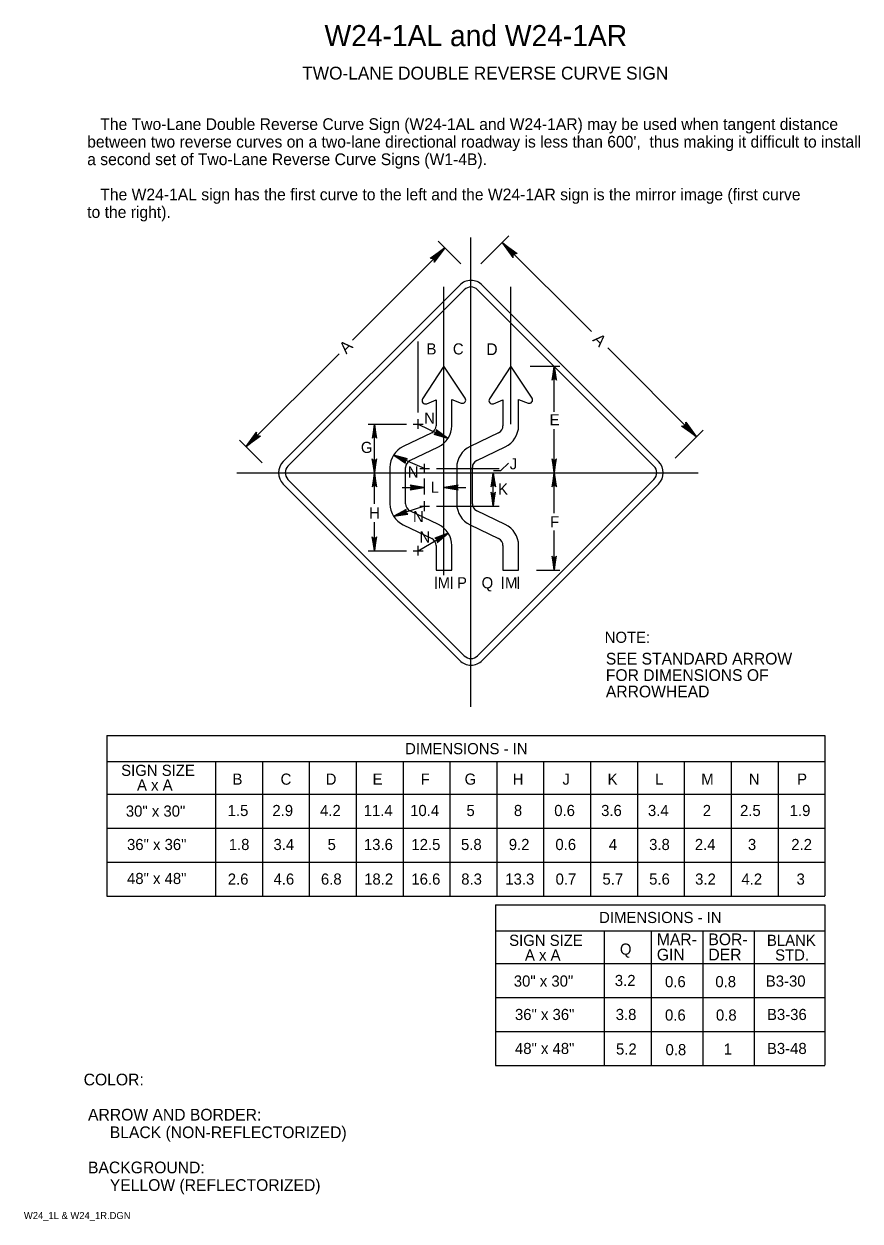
# Model space of a CAD drawing. Extents: x -0.124 to 0.191, y 0.004 to 0.276.
# Drawn here: x 0.0125 to 0.1908, y 0.0039 to 0.2592 of the extents above; entities that cross this region are included whole.
import ezdxf

# ---------------------------------------------------------------- set-up
doc = ezdxf.new("R2010")
doc.units = 0
for name, color, linetype in [('1', 7, 'Continuous'), ('2', 7, 'Continuous'), ('3', 7, 'Continuous')]:
    doc.layers.add(name, color=color, linetype=linetype)

# ---------------------------------------------------------------- blocks, each defined once
blk = doc.blocks.new('RARROW')
at = {"layer": '3'}
for p, q in [((-2.156, 0.28500000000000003), (-2.2665, 0.384625)), ((-2.2665, 0.384625), (0, 0)), ((0, 0), (-2.2665, -0.379125)), ((-2.156, 0.28500000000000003), (-2.075625, 0.12075)), ((0, 0), (-2.156, 0.28500000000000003)), ((-2.14975, -0.2705), (0, 0)), ((-2.075625, 0.12075), (0, 0)), ((0, 0), (-2.074, -0.108)), ((-2.2665, -0.379125), (-2.14975, -0.2705)), ((-2.074, -0.108), (-2.14975, -0.2705))]:
    blk.add_line(p, q, dxfattribs=at)

msp = doc.modelspace()

# ---------------------------------------------------------------- linework, layer by layer
at = {"layer": '1'}
for p, q in [((0.1021023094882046, 0.18627422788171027), (0.09754778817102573, 0.1792997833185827)), ((0.10662950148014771, 0.17945133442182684), (0.1021023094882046, 0.18627422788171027)), ((0.11635231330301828, 0.18627422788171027), (0.11179779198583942, 0.1792997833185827)), ((0.12087950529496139, 0.17945133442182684), (0.11635231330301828, 0.18627422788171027)), ((0.09841935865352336, 0.178251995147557), (0.10043841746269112, 0.17909326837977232)), ((0.10043841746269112, 0.17909326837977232), (0.10043841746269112, 0.1735589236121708)), ((0.10376620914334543, 0.1735589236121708), (0.10376620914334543, 0.17911385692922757)), ((0.10376620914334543, 0.17911385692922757), (0.10579235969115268, 0.1783902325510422)), ((0.11266936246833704, 0.178251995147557), (0.11468842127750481, 0.17909326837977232)), ((0.11468842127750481, 0.17909326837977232), (0.11468842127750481, 0.1735589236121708)), ((0.11801620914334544, 0.1735589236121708), (0.11801620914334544, 0.17911385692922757)), ((0.11801620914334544, 0.17911385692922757), (0.12004236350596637, 0.1783902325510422)), ((0.0955606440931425, 0.17389922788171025), (0.09764397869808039, 0.17389922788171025)), ((0.09660231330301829, 0.17285756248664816), (0.09660231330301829, 0.17494089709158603)), ((0.09949303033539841, 0.17205816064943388), (0.09341002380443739, 0.1691458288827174)), ((0.1137430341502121, 0.17205816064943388), (0.10766002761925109, 0.1691458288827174)), ((0.09484705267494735, 0.16614429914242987), (0.1009300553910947, 0.169056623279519)), ((0.10909705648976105, 0.16614429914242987), (0.11518005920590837, 0.169056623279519)), ((0.09057386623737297, 0.16464352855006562), (0.09057386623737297, 0.15691713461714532)), ((0.09390166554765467, 0.15691712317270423), (0.09390166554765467, 0.1646435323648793)), ((0.09693564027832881, 0.16439922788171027), (0.09901897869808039, 0.16439922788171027)), ((0.0979773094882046, 0.16335755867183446), (0.0979773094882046, 0.16544089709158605)), ((0.10482387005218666, 0.16464352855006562), (0.10482387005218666, 0.15691713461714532)), ((0.10815166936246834, 0.15691712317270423), (0.10815166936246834, 0.1646435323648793)), ((0.09693564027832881, 0.15639922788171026), (0.09901897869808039, 0.15639922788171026)), ((0.0979773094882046, 0.15535756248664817), (0.0979773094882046, 0.15744089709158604)), ((0.10092833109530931, 0.15250771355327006), (0.09484762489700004, 0.15541608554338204)), ((0.11517833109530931, 0.15250771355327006), (0.10909762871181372, 0.15541608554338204)), ((0.0934117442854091, 0.152414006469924), (0.09949245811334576, 0.14950563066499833)), ((0.10766174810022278, 0.152414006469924), (0.11374246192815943, 0.14950563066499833)), ((0.0955606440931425, 0.14689922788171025), (0.09764397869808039, 0.14689922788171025)), ((0.09660231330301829, 0.14585755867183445), (0.09660231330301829, 0.14794089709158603)), ((0.10043841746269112, 0.14800459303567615), (0.10043841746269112, 0.1427751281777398)), ((0.10376620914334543, 0.1427751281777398), (0.10376620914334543, 0.14800458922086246)), ((0.11468842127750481, 0.14800459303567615), (0.11468842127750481, 0.1427751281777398)), ((0.11801620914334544, 0.1427751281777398), (0.11801620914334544, 0.14800458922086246)), ((0.10043841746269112, 0.1427751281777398), (0.10376620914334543, 0.1427751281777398)), ((0.11468842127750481, 0.1427751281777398), (0.11801620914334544, 0.1427751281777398))]:
    msp.add_line(p, q, dxfattribs=at)
for centre, radius, start, end in [((0.0981450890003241, 0.17891023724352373), 0.0007130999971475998, 146.8886580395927, 292.619864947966), ((0.10603220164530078, 0.17906178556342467), 0.0007130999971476, 250.34617594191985, 33.111341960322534), ((0.11239509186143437, 0.17891023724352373), 0.0007130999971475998, 146.8886580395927, 292.619864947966), ((0.12028220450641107, 0.17906178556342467), 0.0007130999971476, 250.34617594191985, 33.111341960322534), ((0.09877451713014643, 0.17355892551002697), 0.0016638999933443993, 295.58345819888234, 359.999999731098), ((0.0987745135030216, 0.17355892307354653), 0.004991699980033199, 295.5834507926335, 0), ((0.11302451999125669, 0.17355892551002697), 0.0016638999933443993, 295.58345819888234, 359.999999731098), ((0.11302451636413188, 0.17355892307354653), 0.004991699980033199, 295.5834507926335, 0), ((0.0955655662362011, 0.16464353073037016), 0.0049916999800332, 115.58345385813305, 180), ((0.10981556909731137, 0.16464353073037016), 0.0049916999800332, 115.58345385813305, 180), ((0.09556556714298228, 0.164643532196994), 0.0016638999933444, 115.58343656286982, 180), ((0.10981557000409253, 0.164643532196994), 0.0016638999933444, 115.58343656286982, 180), ((0.0955655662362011, 0.15691713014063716), 0.0049916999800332, 180.00000202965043, 244.438453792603), ((0.09556556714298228, 0.1569171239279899), 0.001663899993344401, 180, 244.43846100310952), ((0.10981556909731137, 0.15691713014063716), 0.0049916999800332, 180.00000202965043, 244.438453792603), ((0.10981557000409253, 0.1569171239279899), 0.001663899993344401, 180, 244.43846100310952), ((0.0987745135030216, 0.148004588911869), 0.0049916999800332, 0, 64.4384641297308), ((0.11302451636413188, 0.148004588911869), 0.0049916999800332, 0, 64.4384641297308), ((0.09877451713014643, 0.14800459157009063), 0.0016638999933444, 0, 64.43844982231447), ((0.11302451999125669, 0.14800459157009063), 0.0016638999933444, 0, 64.43844982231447)]:
    msp.add_arc(centre, radius, start, end, dxfattribs=at)
at = {"layer": '3'}
for p, q in [((0.10573099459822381, 0.20807195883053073), (0.10088344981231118, 0.21291950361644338)), ((0.10785231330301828, 0.11360347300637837), (0.10785231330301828, 0.21369015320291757)), ((0.10997363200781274, 0.20807195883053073), (0.1159481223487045, 0.21404644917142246)), ((0.13353318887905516, 0.19363295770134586), (0.11453390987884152, 0.2126322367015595)), ((0.08259047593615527, 0.19179810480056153), (0.10229766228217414, 0.2115052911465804)), ((0.06783006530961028, 0.16592839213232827), (0.10544814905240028, 0.20354647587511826)), ((0.06882001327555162, 0.16493844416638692), (0.10643809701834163, 0.20255652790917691)), ((0.1021023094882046, 0.14165792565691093), (0.1021023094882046, 0.2031812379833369)), ((0.10926652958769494, 0.20255652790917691), (0.14688460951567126, 0.16493844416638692)), ((0.1102564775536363, 0.20354647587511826), (0.1478745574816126, 0.16592839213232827)), ((0.11635231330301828, 0.17389922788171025), (0.11635231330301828, 0.2031812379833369)), ((0.09660231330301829, 0.17639922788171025), (0.09660231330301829, 0.1914969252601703)), ((0.05987125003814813, 0.1690788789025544), (0.07971428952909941, 0.18892191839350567)), ((0.15597037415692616, 0.17119577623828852), (0.13701492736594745, 0.19015122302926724)), ((0.12045229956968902, 0.18627422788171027), (0.12683979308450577, 0.18627422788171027)), ((0.12558979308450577, 0.1765), (0.12558979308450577, 0.18627422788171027)), ((0.08596098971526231, 0.17389922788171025), (0.09410231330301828, 0.17389922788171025)), ((0.08725000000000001, 0.1635), (0.08725000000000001, 0.173875)), ((0.09660231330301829, 0.17389923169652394), (0.10295760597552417, 0.17083517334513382)), ((0.12558979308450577, 0.16352422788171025), (0.12558979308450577, 0.17284542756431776)), ((0.1514100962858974, 0.16663549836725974), (0.15738458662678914, 0.1726099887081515)), ((0.06330458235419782, 0.1656455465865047), (0.058457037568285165, 0.1704930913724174)), ((0.0979773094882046, 0.16439923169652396), (0.09132239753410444, 0.1672727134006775)), ((0.057889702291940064, 0.16352422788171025), (0.1563329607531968, 0.16352422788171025)), ((0.08725000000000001, 0.15687500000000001), (0.08725000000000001, 0.1635)), ((0.1004773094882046, 0.16439922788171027), (0.11385231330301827, 0.16439922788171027)), ((0.11260231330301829, 0.15639922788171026), (0.11260231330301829, 0.16352422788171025)), ((0.12558979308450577, 0.154875), (0.12558979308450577, 0.16352422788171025)), ((0.10544814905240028, 0.12350197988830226), (0.06783006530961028, 0.16112006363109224)), ((0.10643809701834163, 0.1244919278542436), (0.06882001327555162, 0.16211001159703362)), ((0.0979773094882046, 0.15889922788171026), (0.0979773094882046, 0.16227422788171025)), ((0.14688460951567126, 0.16211001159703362), (0.10926652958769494, 0.1244919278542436)), ((0.1478745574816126, 0.16112006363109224), (0.1102564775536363, 0.12350197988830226)), ((0.09320617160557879, 0.16037910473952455), (0.0979773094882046, 0.16037910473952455)), ((0.1021023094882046, 0.16037910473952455), (0.10674284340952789, 0.16037910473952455)), ((0.0979773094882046, 0.15639923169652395), (0.09135108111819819, 0.15424221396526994)), ((0.1004773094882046, 0.15639922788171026), (0.11385231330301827, 0.15639922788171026)), ((0.08725000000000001, 0.146875), (0.08725000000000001, 0.1530079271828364)), ((0.0966023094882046, 0.14689923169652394), (0.10301698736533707, 0.15063489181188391)), ((0.12558979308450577, 0.14277422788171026), (0.12558979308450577, 0.15118140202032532)), ((0.08596098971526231, 0.1468809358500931), (0.09410231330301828, 0.1468809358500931)), ((0.10043841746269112, 0.13879908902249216), (0.10043841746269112, 0.14136162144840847)), ((0.10376620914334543, 0.13879908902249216), (0.10376620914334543, 0.14136162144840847)), ((0.11468842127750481, 0.13879908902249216), (0.11468842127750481, 0.14136162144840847)), ((0.11801620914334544, 0.13879908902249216), (0.11801620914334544, 0.14136162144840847)), ((0.12185854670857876, 0.14277422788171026), (0.12683979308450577, 0.14277422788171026)), ((0.030185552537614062, 0.10746646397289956), (0.030185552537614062, 0.07321933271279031)), ((0.030185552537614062, 0.10746646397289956), (0.18336144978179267, 0.10746646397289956)), ((0.18336144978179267, 0.10746646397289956), (0.18336144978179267, 0.0732654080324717)), ((0.030185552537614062, 0.10196646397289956), (0.18336144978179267, 0.10196646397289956)), ((0.05336144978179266, 0.1020154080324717), (0.05336144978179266, 0.0732654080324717)), ((0.06336144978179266, 0.1020154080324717), (0.06336144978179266, 0.0732654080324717)), ((0.07336144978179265, 0.1020154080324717), (0.07336144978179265, 0.0732654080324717)), ((0.08336144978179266, 0.1020154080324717), (0.08336144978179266, 0.0732654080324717)), ((0.09336144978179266, 0.1020154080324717), (0.09336144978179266, 0.0732654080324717)), ((0.10336144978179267, 0.1020154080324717), (0.10336144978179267, 0.0732654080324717)), ((0.11336144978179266, 0.1020154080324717), (0.11336144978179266, 0.0732654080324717)), ((0.12336144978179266, 0.1020154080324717), (0.12336144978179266, 0.0732654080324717)), ((0.13336144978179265, 0.1020154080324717), (0.13336144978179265, 0.0732654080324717)), ((0.14336144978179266, 0.1020154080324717), (0.14336144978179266, 0.0732654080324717)), ((0.15336144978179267, 0.1020154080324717), (0.15336144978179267, 0.0732654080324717)), ((0.16336144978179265, 0.1020154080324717), (0.16336144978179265, 0.0732654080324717)), ((0.17336144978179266, 0.1020154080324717), (0.17336144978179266, 0.0732654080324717)), ((0.030185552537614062, 0.09496646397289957), (0.18336144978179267, 0.09496646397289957)), ((0.030185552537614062, 0.08771646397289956), (0.18336144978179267, 0.08771646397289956)), ((0.030185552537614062, 0.08046646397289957), (0.18336144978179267, 0.08046646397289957)), ((0.030185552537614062, 0.07321646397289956), (0.18336144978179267, 0.07321646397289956)), ((0.11310428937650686, 0.07135381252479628), (0.11310428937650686, 0.03710668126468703)), ((0.11310428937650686, 0.07135381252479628), (0.18332893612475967, 0.07135381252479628)), ((0.18332893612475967, 0.07135381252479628), (0.18332893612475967, 0.03715275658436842)), ((0.11310428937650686, 0.06585381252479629), (0.18332893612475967, 0.06585381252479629)), ((0.13628018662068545, 0.06590275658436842), (0.13628018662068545, 0.03715275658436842)), ((0.14628018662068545, 0.06590275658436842), (0.14628018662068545, 0.03715275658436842)), ((0.15728018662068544, 0.06590275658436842), (0.15728018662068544, 0.03715275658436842)), ((0.16828018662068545, 0.06590275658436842), (0.16828018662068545, 0.03715275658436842)), ((0.11310428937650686, 0.05885381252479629), (0.18332893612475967, 0.05885381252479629)), ((0.11310428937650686, 0.05160381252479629), (0.18332893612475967, 0.05160381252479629)), ((0.11310428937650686, 0.04435381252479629), (0.18332893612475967, 0.04435381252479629)), ((0.11310428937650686, 0.03710381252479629), (0.18332893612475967, 0.03710381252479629))]:
    msp.add_line(p, q, dxfattribs=at)
msp.add_lwpolyline([(0.11262857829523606, 0.16397774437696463), (0.11421019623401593, 0.16397774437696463), (0.11586370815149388, 0.1655573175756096)], dxfattribs=at)
for centre, radius, start, end in [((0.10785231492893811, 0.20114231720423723), 0.0034, 44.99999742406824, 135), ((0.10785231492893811, 0.20114231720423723), 0.002, 44.99999742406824, 135), ((0.070234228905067, 0.16352423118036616), 0.0034, 135.00000000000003, 225.00000000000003), ((0.070234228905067, 0.16352423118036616), 0.002, 135.00000000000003, 225.00000000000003), ((0.14547039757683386, 0.16352423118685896), 0.002, 315.0000025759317, 44.99999726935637), ((0.14547039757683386, 0.16352423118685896), 0.0034000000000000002, 315.0000025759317, 44.99999726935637), ((0.10785231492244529, 0.12590614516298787), 0.0034000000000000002, 225, 315.00000273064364), ((0.10785231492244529, 0.12590614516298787), 0.002, 225, 315.00000273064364)]:
    msp.add_arc(centre, radius, start, end, dxfattribs=at)

# ---------------------------------------------------------------- block references
for p, xscale, yscale, rotation in [((0.10225000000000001, 0.2115), 0.0016545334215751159, 0.0016366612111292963, 44.999999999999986), ((0.114625, 0.2125), 0.0016545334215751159, 0.0016366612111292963, 135.00000000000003), ((0.12562500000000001, 0.18625), 0.0013236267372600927, -0.001309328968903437, 90), ((0.08725000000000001, 0.173875), 0.0013236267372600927, -0.001309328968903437, 90), ((0.155875, 0.17125), 0.0016545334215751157, 0.001636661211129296, -45), ((0.059875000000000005, 0.169125), 0.001654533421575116, 0.001636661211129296, -135), ((0.10287500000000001, 0.170875), 0.0013236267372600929, -0.001309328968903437, -26.26814382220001), ((0.08725000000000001, 0.1635), 0.0013236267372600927, -0.001309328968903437, -90), ((0.091375, 0.16725), 0.0013236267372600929, -0.001309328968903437, 156.1442782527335), ((0.12562500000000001, 0.1635), 0.0013236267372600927, -0.001309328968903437, -90), ((0.08725000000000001, 0.1635), 0.0013236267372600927, -0.001309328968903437, 90), ((0.112625, 0.1635), 0.0013236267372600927, -0.001309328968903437, 90), ((0.12562500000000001, 0.1635), 0.0013236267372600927, -0.001309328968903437, 90), ((0.10212500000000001, 0.160375), 0.0013236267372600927, -0.001309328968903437, 180), ((0.112625, 0.15637500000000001), 0.0013236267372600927, -0.001309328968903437, -90), ((0.091375, 0.15425), 0.0013236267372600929, -0.001309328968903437, -161.77068943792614), ((0.10300000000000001, 0.150625), 0.0013236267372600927, -0.001309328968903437, 30.068101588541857), ((0.08725000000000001, 0.146875), 0.0013236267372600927, -0.001309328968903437, -90), ((0.12562500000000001, 0.14275000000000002), 0.0013236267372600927, -0.001309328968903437, -90)]:
    msp.add_blockref('RARROW', p, dxfattribs=dict(at, xscale=xscale, yscale=yscale, rotation=rotation))
at = {"layer": '3', "xscale": 0.0013236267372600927, "yscale": -0.001309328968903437}
msp.add_blockref('RARROW', (0.097875, 0.160375), dxfattribs=at)

# ---------------------------------------------------------------- texts
at = {"layer": '1'}
for s, height, p in [('W24-1AL and W24-1AR', 0.0045000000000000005, (0.076625, 0.2545)), ('TWO-LANE DOUBLE REVERSE CURVE SIGN', 0.00275025, (0.07187500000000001, 0.247375)), ('NOTE:', 0.0023752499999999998, (0.136375, 0.12725)), ('SEE STANDARD ARROW', 0.0024997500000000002, (0.136625, 0.122625)), ('FOR DIMENSIONS OF', 0.0024997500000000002, (0.136625, 0.11912500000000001)), ('ARROWHEAD', 0.0024997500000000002, (0.136625, 0.115625)), ('COLOR:', 0.0024997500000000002, (0.02525, 0.032875)), (' ARROW AND BORDER:', 0.0024997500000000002, (0.02525, 0.025375)), ('      BLACK (NON-REFLECTORIZED)', 0.0024997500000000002, (0.02525, 0.021625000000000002)), (' BACKGROUND:', 0.0024997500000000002, (0.02525, 0.014125)), ('      YELLOW (REFLECTORIZED)', 0.0024997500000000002, (0.02525, 0.010375)), ('W24_1L & W24_1R.DGN', 0.0015, (0.0125, 0.004375))]:
    msp.add_text(s, height=height, dxfattribs=at).set_placement(p)
at = {"layer": '2'}
for s, p in [('   The Two-Lane Double Reverse Curve Sign (W24-1AL and W24-1AR) may be used when tangent distance', (0.026000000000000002, 0.23662525)), ("between two reverse curves on a two-lane directional roadway is less than 600',  thus making it difficult to install ", (0.026000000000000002, 0.23287549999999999)), ('a second set of Two-Lane Reverse Curve Signs (W1-4B).', (0.026000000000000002, 0.22912575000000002)), ('   The W24-1AL sign has the first curve to the left and the W24-1AR sign is the mirror image (first curve ', (0.026000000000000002, 0.22162625)), ('to the right).', (0.026000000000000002, 0.2178765))]:
    msp.add_text(s, height=0.0024997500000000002, dxfattribs=at).set_placement(p)
at = {"layer": '3'}
for rotation, p in [(315, (0.133625, 0.19175)), (45, (0.08125, 0.18875))]:
    msp.add_text('A', height=0.0024997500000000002, rotation=rotation, dxfattribs=at).set_placement(p)
for s, height, p in [('B', 0.0023752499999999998, (0.098375, 0.18875)), ('C', 0.0023752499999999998, (0.10400000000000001, 0.18875)), ('D', 0.0024997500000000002, (0.111125, 0.18862500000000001)), ('N', 0.0023752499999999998, (0.097875, 0.17400000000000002)), ('E', 0.0023752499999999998, (0.124625, 0.173625)), ('G', 0.0023752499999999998, (0.084375, 0.16775)), ('J', 0.0023752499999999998, (0.116125, 0.16425)), ('N', 0.0023752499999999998, (0.094375, 0.1625)), ('L', 0.0023752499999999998, (0.09925, 0.15925)), ('K', 0.0023752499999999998, (0.113625, 0.15887500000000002)), ('H', 0.0023752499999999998, (0.08612500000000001, 0.15375)), ('N', 0.0023752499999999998, (0.0955, 0.153)), ('F', 0.0023752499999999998, (0.12475, 0.151875)), ('N', 0.0023752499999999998, (0.096875, 0.148625)), ('M', 0.0023752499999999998, (0.10075, 0.138875)), ('P', 0.0023752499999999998, (0.104875, 0.138875)), ('Q', 0.0023752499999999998, (0.110125, 0.138875)), ('M', 0.0023752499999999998, (0.115125, 0.138875)), ('DIMENSIONS - IN', 0.0023752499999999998, (0.09381579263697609, 0.10350000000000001)), ('SIGN SIZE', 0.0023752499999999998, (0.03325, 0.098875)), ('A x A', 0.0023752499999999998, (0.036625, 0.09575)), ('B', 0.0023752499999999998, (0.057, 0.097)), ('C', 0.0023752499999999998, (0.06725, 0.097)), ('D', 0.0023752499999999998, (0.076875, 0.097)), ('E', 0.0023752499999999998, (0.08687500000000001, 0.097)), ('F', 0.0023752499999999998, (0.097125, 0.097)), ('G', 0.0023752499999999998, (0.1065, 0.097)), ('H', 0.0023752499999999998, (0.11675, 0.097)), ('J', 0.0023752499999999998, (0.12737500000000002, 0.097)), ('K', 0.0023752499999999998, (0.137, 0.097)), ('L', 0.0023752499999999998, (0.147125, 0.097)), ('M', 0.0023752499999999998, (0.15697999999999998, 0.097)), ('N', 0.0023752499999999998, (0.16711504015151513, 0.097)), ('P', 0.0023752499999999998, (0.17742873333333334, 0.097)), ('30" x 30"', 0.0023752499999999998, (0.034245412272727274, 0.090187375)), ('1.5', 0.0023752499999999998, (0.05596232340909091, 0.090312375)), ('2.9', 0.0023752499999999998, (0.06549711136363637, 0.090312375)), ('4.2', 0.0023752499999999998, (0.07566997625, 0.090312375)), ('11.4', 0.0023752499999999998, (0.08497815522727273, 0.090312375)), ('10.4', 0.0023752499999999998, (0.0948872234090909, 0.090312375)), ('5', 0.0023752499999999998, (0.10689994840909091, 0.090312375)), ('8', 0.0023752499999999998, (0.11700911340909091, 0.090312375)), ('0.6', 0.0023752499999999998, (0.1256185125, 0.090312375)), ('3.6', 0.0023752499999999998, (0.1356185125, 0.090312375)), ('3.4', 0.0023752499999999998, (0.14560699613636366, 0.090312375)), ('2', 0.0023752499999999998, (0.15730014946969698, 0.090312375)), ('2.5', 0.0023752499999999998, (0.1652463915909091, 0.090312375)), ('1.9', 0.0023752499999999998, (0.1758380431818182, 0.090312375)), ('36" x 36"', 0.0023752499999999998, (0.034495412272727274, 0.08306237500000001)), ('1.8', 0.0023752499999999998, (0.05619648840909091, 0.08306237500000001)), ('3.4', 0.0023752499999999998, (0.06573199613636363, 0.08306237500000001)), ('5', 0.0023752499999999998, (0.07727494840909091, 0.08306237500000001)), ('13.6', 0.0023752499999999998, (0.08502373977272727, 0.08306237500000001)), ('12.5', 0.0023752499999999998, (0.09515161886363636, 0.08306237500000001)), ('5.8', 0.0023752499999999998, (0.10573055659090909, 0.08306237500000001)), ('9.2', 0.0023752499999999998, (0.11591997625, 0.08306237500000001)), ('0.6', 0.0023752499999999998, (0.1258685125, 0.08306237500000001)), ('4', 0.0023752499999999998, (0.13726055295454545, 0.08306237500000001)), ('3.8', 0.0023752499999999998, (0.1458555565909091, 0.08306237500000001)), ('2.4', 0.0023752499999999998, (0.15560699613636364, 0.08306237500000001)), ('3', 0.0023752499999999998, (0.1669316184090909, 0.08306237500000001)), ('2.2', 0.0023752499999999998, (0.17616997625, 0.08306237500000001)), ('48" x 48"', 0.0023752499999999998, (0.034495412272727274, 0.075812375)), ('2.6', 0.0023752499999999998, (0.0559935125, 0.075687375)), ('4.6', 0.0023752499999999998, (0.06574351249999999, 0.075687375)), ('6.8', 0.0023752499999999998, (0.07585555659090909, 0.075687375)), ('18.2', 0.0023752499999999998, (0.08507520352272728, 0.075687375)), ('16.6', 0.0023752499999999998, (0.09514873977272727, 0.075687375)), ('8.3', 0.0023752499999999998, (0.10577806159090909, 0.075687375)), ('13.3', 0.0023752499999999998, (0.11518328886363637, 0.075687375)), ('0.7', 0.0023752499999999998, (0.12590414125, 0.075687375)), ('5.7', 0.0023752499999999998, (0.13590414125, 0.075687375)), ('5.6', 0.0023752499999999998, (0.14586851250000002, 0.075687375)), ('3.2', 0.0023752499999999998, (0.15566997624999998, 0.075687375)), ('4.2', 0.0023752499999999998, (0.16554497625, 0.075687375)), ('3', 0.0023752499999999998, (0.1773066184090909, 0.075687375)), ('DIMENSIONS - IN', 0.0023752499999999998, (0.13519159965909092, 0.0675)), ('SIGN SIZE', 0.0023752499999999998, (0.116, 0.062625)), ('MAR-', 0.0024997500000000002, (0.1475, 0.06277729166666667)), ('BOR-', 0.0024997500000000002, (0.1585, 0.06277729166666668)), ('BLANK', 0.0023752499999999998, (0.1709820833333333, 0.062625)), ('A x A', 0.0023752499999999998, (0.11937500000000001, 0.059500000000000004)), ('Q', 0.0023752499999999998, (0.139625, 0.06075)), ('GIN', 0.0024997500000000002, (0.1475, 0.05952729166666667)), ('DER', 0.0024997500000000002, (0.1585, 0.05952729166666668)), ('STD.', 0.0023752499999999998, (0.17273208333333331, 0.059500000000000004)), ('30" x 30"', 0.0023752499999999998, (0.11699541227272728, 0.053937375)), ('3.2', 0.0023752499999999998, (0.13854497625, 0.054062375)), ('0.6', 0.0023752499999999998, (0.1492435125, 0.053812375)), ('0.8', 0.0023752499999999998, (0.1599805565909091, 0.053812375)), ('B3-30', 0.0023752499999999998, (0.17074638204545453, 0.053937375)), ('36" x 36"', 0.0023752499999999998, (0.11724541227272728, 0.046812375)), ('3.8', 0.0023752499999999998, (0.1387305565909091, 0.046812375)), ('0.6', 0.0023752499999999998, (0.1492435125, 0.046687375)), ('0.8', 0.0023752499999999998, (0.16010555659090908, 0.046687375)), ('B3-36', 0.0023752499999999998, (0.17100142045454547, 0.046812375)), ('48" x 48"', 0.0023752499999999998, (0.11724541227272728, 0.039562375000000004)), ('5.2', 0.0023752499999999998, (0.13879497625, 0.039437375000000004)), ('0.8', 0.0023752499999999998, (0.1493555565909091, 0.039312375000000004)), ('1', 0.0023752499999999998, (0.16176895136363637, 0.039437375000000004)), ('B3-48', 0.0023752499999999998, (0.17098846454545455, 0.039562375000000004))]:
    msp.add_text(s, height=height, dxfattribs=at).set_placement(p)

doc.saveas('drawing.dxf')
